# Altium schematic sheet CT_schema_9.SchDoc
size 274 x 160 mm
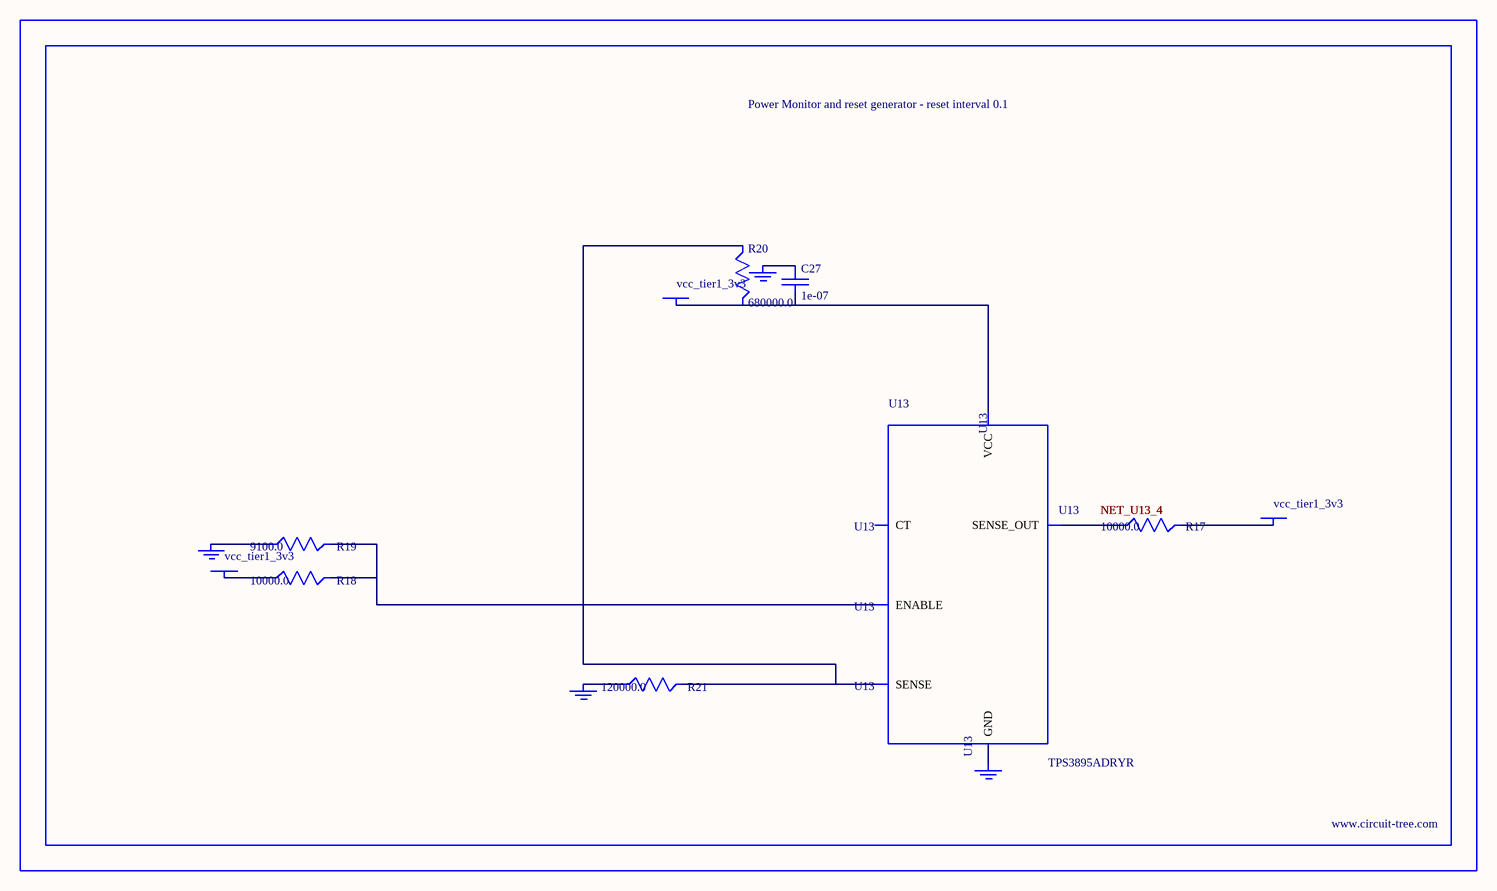
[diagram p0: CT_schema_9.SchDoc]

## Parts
BORDER8  (no value)
C27  1e-07  [C0402]
GND_INSTANCE_8_0  (no value)
GND_INSTANCE_8_1  (no value)
GND_INSTANCE_8_2  (no value)
GND_INSTANCE_8_3  (no value)
POWER_INSTANCE_8_0  vcc_tier1_3v3
POWER_INSTANCE_8_1  vcc_tier1_3v3
POWER_INSTANCE_8_2  vcc_tier1_3v3
R17  10000.0  [R0603]
R18  10000.0  [R0603]
R19  9100.0  [R0603]
R20  680000.0  [R0603]
R21  120000.0  [R0603]
U13  TPS3895ADRYR  [SON-6]

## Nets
NetC27_1: C27.1 GND_INSTANCE_8_2.0(GND)
NetC27_2: C27.2 POWER_INSTANCE_8_2.0(PWR) R20.2 U13.6(VCC)
NetGND_INSTANCE_8_0_0: GND_INSTANCE_8_0.0(GND) R19.1
NetGND_INSTANCE_8_1_0: GND_INSTANCE_8_1.0(GND) R21.1
NetGND_INSTANCE_8_3_0: GND_INSTANCE_8_3.0(GND) U13.2(GND)
NetPOWER_INSTANCE_8_0_0: POWER_INSTANCE_8_0.0(PWR) R18.1
NetPOWER_INSTANCE_8_1_0: POWER_INSTANCE_8_1.0(PWR) R17.2
NetR17_1: R17.1 U13.4(SENSE_OUT)
NetR18_2: R18.2 R19.2 U13.1(ENABLE)
NetR20_1: R20.1 R21.2 U13.3(SENSE)

Not connected (* = marked no-connect by the designer): U13 5(CT)

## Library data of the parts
BORDER8 = BORDER_PAGE8
C27 = C0402C104K3RACTU
GND_INSTANCE_8_0-GND_INSTANCE_8_3 = GND
POWER_INSTANCE_8_0-POWER_INSTANCE_8_2 = PWR
R17 R18 = RC0603JR-0710KL
R19 = RC0603JR-079K1L
R20 = RC0603JR-07680KL
R21 = RC0603JR-07120KL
